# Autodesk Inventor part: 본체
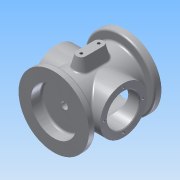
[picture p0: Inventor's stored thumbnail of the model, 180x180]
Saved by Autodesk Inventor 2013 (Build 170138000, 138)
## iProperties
Created: 2018-02
Part Number: 본체
Material: 알루미늄 6061
Document SubType Name: Modeling
Designer: Administrator
Density: 2.71 g/cm^3
Mass: 771.665 g
Surface Area: 822.305 cm^2
Volume: 284.747 cm^3
Author: Administrator
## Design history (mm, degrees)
sketch "스케치1"
  geometry: L1 (0, 0)-(0, 54); L2 (0, 54)-(-52.5, 54); L3 (-52.5, 54)-(-52.5, 44); L4 (-52.5, 44)-(-38, 44); L5 (-38, 44)-(-38, 0); L6 (-38, 0)-(0, 0)
  constraints: 12 end point, 3 parallel, 2 perpendicular, 1 vertical
  dimensions: "d0" = 54 distance of L1.start L1.end; "d1" = 10 distance of L2.end L3.end; "d2" = 52.5 distance of L1.end L2.end; "d3" = 76 diameter of L5 L1
revolve "회전1" sketch "스케치1" stored, may be unused: angle "d4" = 90 deg
fillet "모깎기1" dims "d5" = 3
fillet "모깎기2" dims "d6" = 3
sketch "스케치2"
  geometry: C1 r 35 at (0, 0); 1 further point
  constraints: 1 centre point, 1 coincident
  dimensions: "d7" = 70 diameter of C1
extrude "돌출1" join sketch "스케치2" stored distance "d9" = 100; taper "d10" = 0 deg
hole "구멍1" diameter "d13" = 66; stored, may be unused: countersink angle "d17" = 90 deg, drill point angle "d19" = 0 deg; dims "d11" = 10, "d12" = 10, "d14" = 6, "d15" = 74, "d16" = 7, "d18" = 86
hole "구멍2" diameter "d22" = 10; stored, may be unused: countersink angle "d26" = 90 deg, drill point angle "d28" = 0 deg; dims "d20" = 10, "d21" = 10, "d23" = 6, "d24" = 68, "d25" = 16, "d27" = 86
chamfer "모따기1" distance "d29" = 1; stored, may be unused: second distance "d30" = 2, angle "d31" = 45 deg
fillet "모깎기3" dims "d32" = 3
fillet "모깎기4" dims "d33" = 3
hole "구멍3" diameter "d36" = 48; stored, may be unused: countersink angle "d40" = 90 deg, drill point angle "d42" = 0 deg; dims "d34" = 10, "d35" = 10, "d37" = 6, "d38" = 68, "d39" = 16, "d41" = 86
fillet "모깎기6" dims "d44" = 3
node "작업 평면2"
sketch "스케치3"
  geometry: L1 (-7, 13)-(-7, -13); L2 (7, 13)-(7, -13); A1 r 7 centre (0, 13) between (-7, 13) and (7, 13); A2 r 7 centre (0, -13) between (-7, -13) and (7, -13); 2 further points
  constraints: 4 end point, 4 point on circle, 3 tangent, 2 centre point, 2 vertical alignment, 1 equal radius, 1 horizontal alignment, 1 midpoint, 1 parallel
  dimensions: "d47" = 14 diameter of A1; "d49" = 40 dimension on A2 A1
extrude "돌출2" join sketch "스케치3" stored distance "d50" = 100; taper "d51" = 15 deg
sketch "스케치4"
  geometry: A1 r 7 centre (0, -13) between (-7, -13) and (7, -13) reference; A2 r 7 centre (0, 13) between (7, 13) and (-7, 13) reference; 3 further points
  constraints: 2 coincident
hole "구멍4" sketch "스케치4" at (0, 13), (0, -13) diameter "d52" = 4.134; stored, may be unused: countersink angle "d56" = 90 deg, drill point angle "d58" = 118 deg; dims "d53" = 6, "d54" = 68, "d55" = 16, "d57" = 8
chamfer "모따기2" distance "d59" = 1; stored, may be unused: second distance "d60" = 2, angle "d61" = 45 deg
sketch "스케치5"
  geometry: C1 r 35 at (0, 0) reference; 1 further point
  constraints: 1 vertical alignment
  dimensions: "d62" = 29 distance of C1.centre point (0, 29)
hole "구멍5" sketch "스케치5" at (0, 29) diameter "d63" = 3.242; stored, may be unused: countersink angle "d67" = 90 deg, drill point angle "d69" = 118 deg; dims "d64" = 4, "d65" = 68, "d66" = 16, "d68" = 6
sketch "스케치6"
  geometry: C1 r 52.5 at (0, 0) reference; 1 further point
  constraints: 1 vertical alignment
  dimensions: "d73" = 45 distance of point (0, 45) C1.centre
hole "구멍6" sketch "스케치6" at (0, 45) diameter "d74" = 3.242; stored, may be unused: countersink angle "d78" = 90 deg, drill point angle "d80" = 118 deg; dims "d75" = 4, "d76" = 68, "d77" = 16, "d79" = 6
sketch "스케치7"
  geometry: C1 r 41 at (0, 0) reference; C2 r 43 at (0, 0)
  constraints: 1 centre point, 1 coincident, 1 other
  dimensions: "d84" = 86 diameter of C2
feature "엠보싱1" sketch "스케치7" dims "d87" = 0.5, "d88" = 0
fillet "모깎기7" dims "d89" = 3
node "솔리드1"
mirror "대칭1"
pattern_circular "원형 패턴1" dims angle "d71" = 360 deg
mirror "대칭2"
pattern_circular "원형 패턴2" dims angle "d82" = 360 deg
other parameters: "d46" = 55
